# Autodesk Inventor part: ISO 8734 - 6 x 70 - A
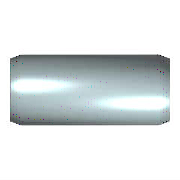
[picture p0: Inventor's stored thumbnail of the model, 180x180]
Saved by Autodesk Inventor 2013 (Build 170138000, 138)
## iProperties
IsCustomPart: 0
Created: 2012-02
Part Number: ISO 8734 - 6 x 70 - A
Material: Stahl
Description: Zylinderstift
Document SubType Name: Modeling
Standard: ISO 8734
Designer: rYan
Standards Organization: DIN
Language: de-DE
Size Designation: 6 x 70 - A
Categories: <MemberInstance><Categories><Category DisplayName="Verbindungselemente" InternalName="e4da775c-781d-43d5-af7c-5136215cf5a6" Mnemonic="FSTN"><Category DisplayNam
Density: 7.85 g/cm^3
Mass: 15.3728 g
Surface Area: 13.519 cm^2
Volume: 1.95832 cm^3
Author: rYan
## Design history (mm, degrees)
sketch "Skizze"
  geometry: C1 r 3 at (0, 0); 1 further point
  constraints: 1 centre point, 1 coincident
  dimensions: "d1" = 6 diameter of C1 (= NND)
extrude "Körper" new body sketch "Skizze" distance "d2" = 70 (= NLG); taper "d3" = 0 deg
body "Solid1"
chamfer "Fase1" distance "d4" = 2.1 (= PHH); stored, may be unused: angle "d5" = 15 deg (= FAWI), second distance "d11" = 2.1 (= PHH)
chamfer "Fase2" distance "d8" = 2.1 (= PHH); stored, may be unused: angle "d9" = 15 deg (= FAWI), second distance "d12" = 2.1 (= PHH)
other parameters: "NND" = 6 [user parameter; used in 1 equation term], "NLG" = 70 [user parameter; used in 1 equation term], "PHH" = 2.1 [user parameter; used in 5 equation terms], "FAWI" = 15 deg [user parameter; used in 2 equation terms], "d13" = 0, "d15" = 0, "d16" = 0, "PHH2" = 2.1 (= PHH) [user parameter], "FAWI2" = 15 deg [user parameter]
